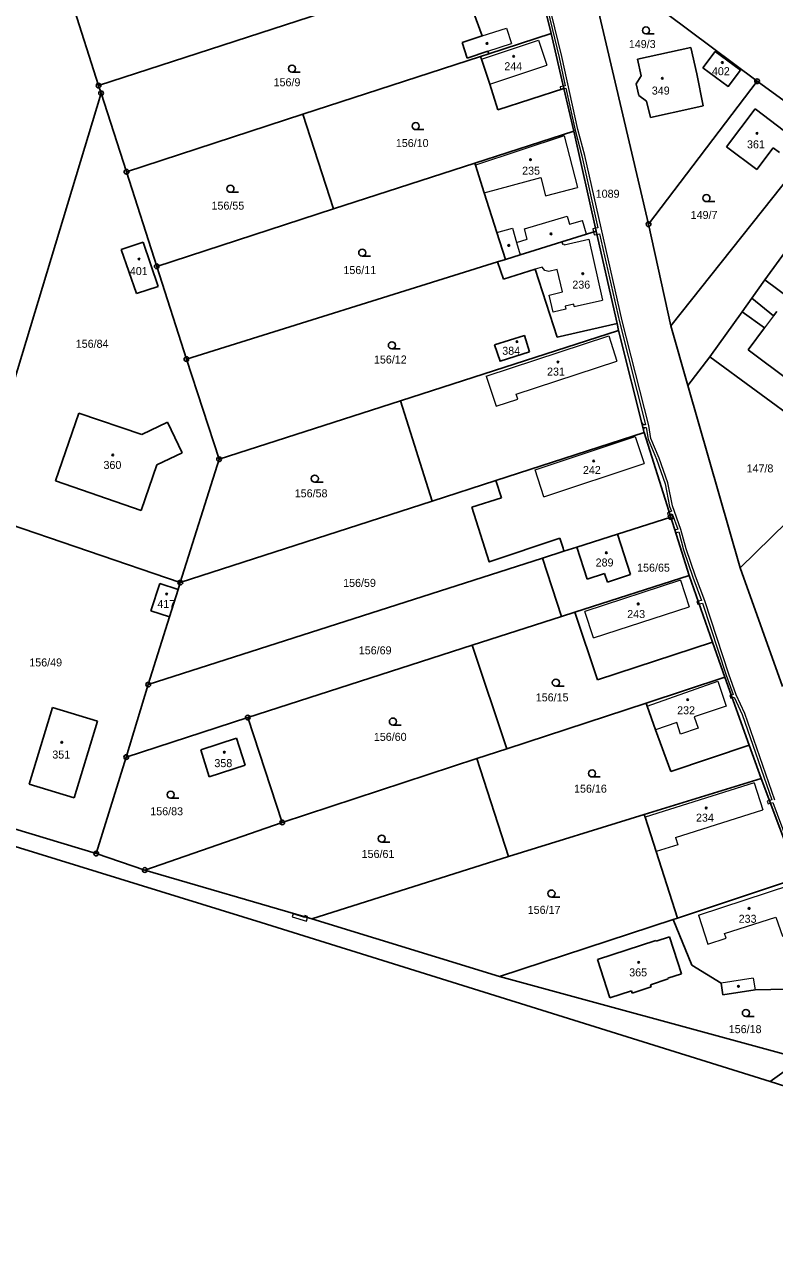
# Model space of a CAD drawing. Extents: x -694609 to -690140, y -1033292 to -1029794.
# Drawn here: x -693108.5 to -692949.2, y -1031786.2 to -1031527.4 of the extents above; entities that cross this region are included whole.
import ezdxf
from ezdxf.enums import TextEntityAlignment as Align

# ---------------------------------------------------------------- set-up
doc = ezdxf.new("R2010")
doc.units = 0
doc.header["$LTSCALE"] = 0.68
for name, color, linetype, lineweight in [('1', 7, 'Continuous', 25), ('13', 7, 'Continuous', 13), ('3', 7, 'Continuous', 25), ('4', 7, 'Continuous', 13), ('5', 7, 'Continuous', 25), ('8', 7, 'Continuous', 25)]:
    doc.layers.add(name, color=color, linetype=linetype, lineweight=lineweight)
doc.layers.add('2', color=7, linetype='Continuous')

msp = doc.modelspace()

# ---------------------------------------------------------------- linework, layer by layer
at = {"layer": '1'}
for p, q in [((-692996.59, -1031529.38), (-693001.15, -1031510.6)), ((-692982.32, -1031517.41), (-692952.88, -1031539.48)), ((-693032.75, -1031520.89), (-693092.7, -1031540.43)), ((-693014.39, -1031521.24), (-693011.22, -1031529.87)), ((-693092.7, -1031540.43), (-693098.34, -1031522.85)), ((-692975.92, -1031569.87), (-692987.13, -1031522.11)), ((-693009.82, -1031533.69), (-692996.59, -1031529.38)), ((-692996.59, -1031529.38), (-692993.89, -1031541.03)), ((-693015.51, -1031531.27), (-693011.22, -1031529.87)), ((-693014.44, -1031534.56), (-693015.51, -1031531.27)), ((-693049.32, -1031546.52), (-693011.57, -1031534.26)), ((-693014.44, -1031534.56), (-693010.03, -1031533.12)), ((-693011.57, -1031534.26), (-693009.82, -1031533.69)), ((-693011.39, -1031534.77), (-693011.57, -1031534.26)), ((-693010.03, -1031533.12), (-693009.82, -1031533.69)), ((-692966.91, -1031532.31), (-692978.28, -1031534.82)), ((-692965.67, -1031537.94), (-692966.91, -1031532.31)), ((-693011.39, -1031534.77), (-693009.62, -1031540.12)), ((-692978.28, -1031534.82), (-692977.51, -1031538.37)), ((-692977.51, -1031538.37), (-692978.57, -1031540.08)), ((-692975.92, -1031569.87), (-692952.88, -1031539.48)), ((-692964.32, -1031544.75), (-692965.67, -1031537.94)), ((-692938.37, -1031550.06), (-692952.88, -1031539.48)), ((-693092.18, -1031542.05), (-693137.04, -1031690.35)), ((-693092.18, -1031542.05), (-693092.7, -1031540.43)), ((-693086.77, -1031558.74), (-693092.18, -1031542.05)), ((-693009.62, -1031540.12), (-693007.9, -1031545.56)), ((-693007.9, -1031545.56), (-692993.89, -1031541.03)), ((-692993.89, -1031541.03), (-692991.79, -1031550.1)), ((-692978.57, -1031540.08), (-692978.01, -1031542.52)), ((-692978.01, -1031542.52), (-692976.32, -1031543.72)), ((-692976.32, -1031543.72), (-692975.53, -1031547.21)), ((-692966.55, -1031545.23), (-692964.32, -1031544.75)), ((-693086.77, -1031558.74), (-693049.32, -1031546.52)), ((-693049.32, -1031546.52), (-693042.84, -1031566.57)), ((-692975.53, -1031547.21), (-692966.55, -1031545.23)), ((-692959.34, -1031553.42), (-692953.28, -1031545.38)), ((-692953.28, -1031545.38), (-692945.56, -1031551.2)), ((-692991.79, -1031550.1), (-693012.81, -1031556.88)), ((-692987.06, -1031571.33), (-692991.79, -1031550.1)), ((-692938.37, -1031550.06), (-692971.22, -1031591.47)), ((-692952.95, -1031558.23), (-692959.34, -1031553.42)), ((-692949.47, -1031553.61), (-692952.95, -1031558.23)), ((-692948.12, -1031554.62), (-692949.47, -1031553.61)), ((-693012.81, -1031556.88), (-693042.84, -1031566.57)), ((-693012.81, -1031556.88), (-693012.69, -1031557.29)), ((-693012.69, -1031557.29), (-693010.84, -1031563.21)), ((-693080.36, -1031578.82), (-693086.77, -1031558.74)), ((-693010.84, -1031563.21), (-693008.14, -1031571.66)), ((-692939.33, -1031565.31), (-692951.21, -1031581.69)), ((-693042.84, -1031566.57), (-693080.36, -1031578.82)), ((-692971.22, -1031591.47), (-692975.92, -1031569.87)), ((-693008.14, -1031571.66), (-693006.32, -1031577.35)), ((-692989.09, -1031571.97), (-692994.33, -1031573.61)), ((-692987.06, -1031571.33), (-692989.09, -1031571.97)), ((-692982.61, -1031590.99), (-692987.06, -1031571.33)), ((-693087.89, -1031575.21), (-693083.26, -1031573.68)), ((-693084.63, -1031584.58), (-693087.89, -1031575.21)), ((-693083.26, -1031573.68), (-693080.08, -1031583.08)), ((-693001.14, -1031575.73), (-693003.19, -1031576.37)), ((-692994.33, -1031573.61), (-693001.14, -1031575.73)), ((-693007.96, -1031577.86), (-693074.04, -1031598.52)), ((-693006.32, -1031577.35), (-693007.96, -1031577.86)), ((-693006.73, -1031581.52), (-693007.96, -1031577.86)), ((-693003.19, -1031576.37), (-693006.32, -1031577.35)), ((-693074.04, -1031598.52), (-693080.36, -1031578.82)), ((-692999.96, -1031579.41), (-693006.73, -1031581.52)), ((-692999.96, -1031579.41), (-692995.35, -1031593.86)), ((-693080.08, -1031583.08), (-693084.63, -1031584.58)), ((-692953.98, -1031585.61), (-692951.21, -1031581.69)), ((-692951.21, -1031581.69), (-692920.32, -1031604.87)), ((-692956.05, -1031588.46), (-692953.98, -1031585.61)), ((-692949.38, -1031589.37), (-692953.98, -1031585.61)), ((-692962.9, -1031598.03), (-692956.05, -1031588.46)), ((-692951.27, -1031591.88), (-692956.05, -1031588.46)), ((-692948.67, -1031588.42), (-692949.38, -1031589.37)), ((-692995.35, -1031593.86), (-692982.61, -1031590.99)), ((-692982.28, -1031592.45), (-692982.61, -1031590.99)), ((-692967.59, -1031604.13), (-692971.22, -1031591.47)), ((-693028.58, -1031607.39), (-692982.28, -1031592.45)), ((-692976.87, -1031614.09), (-692982.28, -1031592.45)), ((-692951.27, -1031591.88), (-692954.78, -1031596.58)), ((-692954.78, -1031596.58), (-692945.81, -1031603.31)), ((-693067.1, -1031619.81), (-693074.04, -1031598.52)), ((-692962.9, -1031598.03), (-692967.59, -1031604.13)), ((-692933.59, -1031619.64), (-692962.9, -1031598.03)), ((-692956.5, -1031642.88), (-692967.59, -1031604.13)), ((-693058.18, -1031718.22), (-693416.83, -1031607.47)), ((-693067.1, -1031619.81), (-693028.58, -1031607.39)), ((-693028.58, -1031607.39), (-693021.89, -1031628.69)), ((-693096.87, -1031610.05), (-693101.84, -1031624.4)), ((-693083.5, -1031614.53), (-693096.87, -1031610.05)), ((-693078.05, -1031611.96), (-693083.5, -1031614.53)), ((-693074.92, -1031618.41), (-693078.05, -1031611.96)), ((-692976.87, -1031614.09), (-693008.34, -1031624.3)), ((-692971.22, -1031632.08), (-692976.87, -1031614.09)), ((-693080.3, -1031621.02), (-693074.92, -1031618.41)), ((-693075.34, -1031646.02), (-693067.1, -1031619.81)), ((-693083.63, -1031630.7), (-693080.3, -1031621.02)), ((-693101.84, -1031624.4), (-693083.63, -1031630.7)), ((-693008.34, -1031624.3), (-693021.89, -1031628.69)), ((-693007.16, -1031628.01), (-693008.34, -1031624.3)), ((-693021.89, -1031628.69), (-693075.34, -1031646.02)), ((-693013.44, -1031629.97), (-693007.16, -1031628.01)), ((-692956.5, -1031642.88), (-692942.66, -1031629.3)), ((-693114.36, -1031632.65), (-693075.34, -1031646.02)), ((-692971.22, -1031632.08), (-692982.48, -1031635.69)), ((-692967.28, -1031644.48), (-692971.22, -1031632.08)), ((-692982.48, -1031635.69), (-692991.13, -1031638.47)), ((-692979.72, -1031644.3), (-692982.48, -1031635.69)), ((-692994.79, -1031636.57), (-692994.08, -1031638.71)), ((-692998.42, -1031640.85), (-693082.14, -1031667.69)), ((-692993.88, -1031639.35), (-692998.42, -1031640.85)), ((-692998.42, -1031640.85), (-692994.42, -1031653.21)), ((-692994.08, -1031638.71), (-692993.88, -1031639.35)), ((-692991.13, -1031638.47), (-692993.88, -1031639.35)), ((-692991.13, -1031638.47), (-692988.94, -1031645.28)), ((-692947.47, -1031668.1), (-692956.5, -1031642.88)), ((-692967.28, -1031644.48), (-692991.55, -1031652.29)), ((-692988.94, -1031645.28), (-692985.25, -1031644.1)), ((-692985.25, -1031644.1), (-692984.67, -1031645.89)), ((-692984.67, -1031645.89), (-692979.72, -1031644.3)), ((-692962.32, -1031658.64), (-692967.28, -1031644.48)), ((-693081.58, -1031652.04), (-693079.72, -1031646.22)), ((-693079.72, -1031646.22), (-693075.8, -1031647.47)), ((-693077.62, -1031653.29), (-693082.14, -1031667.69)), ((-693077.62, -1031653.29), (-693081.58, -1031652.04)), ((-692994.42, -1031653.21), (-693013.35, -1031659.31)), ((-692991.55, -1031652.29), (-692994.42, -1031653.21)), ((-692991.55, -1031652.29), (-692986.76, -1031666.7)), ((-692986.76, -1031666.7), (-692962.32, -1031658.64)), ((-692959.71, -1031666.1), (-692962.32, -1031658.64)), ((-693013.35, -1031659.31), (-693061.03, -1031674.69)), ((-693013.35, -1031659.31), (-693006.04, -1031681.32)), ((-692976.45, -1031671.6), (-692959.71, -1031666.1)), ((-692954.52, -1031680.58), (-692959.71, -1031666.1)), ((-693086.84, -1031683.08), (-693082.14, -1031667.69)), ((-693006.04, -1031681.32), (-692976.45, -1031671.6)), ((-692976.22, -1031672.24), (-692976.45, -1031671.6)), ((-693107.47, -1031688.82), (-693102.49, -1031672.52)), ((-693102.49, -1031672.52), (-693092.93, -1031675.45)), ((-692976.22, -1031672.24), (-692974.44, -1031677.28)), ((-693092.93, -1031675.45), (-693097.9, -1031691.72)), ((-693086.84, -1031683.08), (-693061.03, -1031674.69)), ((-693061.03, -1031674.69), (-693053.69, -1031696.97)), ((-693071, -1031681.54), (-693063.4, -1031679.06)), ((-693063.4, -1031679.06), (-693061.54, -1031684.8)), ((-692974.44, -1031677.28), (-692971.19, -1031686.15)), ((-693071, -1031681.54), (-693069.19, -1031687.28)), ((-693012.37, -1031683.38), (-693006.04, -1031681.32)), ((-693093.2, -1031703.58), (-693086.84, -1031683.08)), ((-693069.19, -1031687.28), (-693061.54, -1031684.8)), ((-693053.69, -1031696.97), (-693012.37, -1031683.38)), ((-693012.37, -1031683.38), (-693005.65, -1031704.18)), ((-693097.9, -1031691.72), (-693107.47, -1031688.82)), ((-692976.82, -1031695.29), (-692951.99, -1031687.63)), ((-692944.11, -1031708.76), (-692951.99, -1031687.63)), ((-693132.25, -1031691.79), (-693093.2, -1031703.58)), ((-693082.89, -1031707.08), (-693053.69, -1031696.97)), ((-693005.65, -1031704.18), (-692976.82, -1031695.29)), ((-692976.62, -1031695.82), (-692976.82, -1031695.29)), ((-692974.33, -1031703.16), (-692976.62, -1031695.82)), ((-693093.2, -1031703.58), (-693082.89, -1031707.08)), ((-693047.4, -1031717.46), (-693005.65, -1031704.18)), ((-692974.33, -1031703.16), (-692969.74, -1031717.28)), ((-693047.4, -1031717.46), (-693082.89, -1031707.08)), ((-692944.11, -1031708.76), (-692969.74, -1031717.28)), ((-692950.08, -1031751.98), (-693058.18, -1031718.22)), ((-693007.59, -1031729.72), (-693047.4, -1031717.46)), ((-693007.59, -1031729.72), (-692970.7, -1031717.6)), ((-692969.74, -1031717.28), (-692970.7, -1031717.6)), ((-692970.7, -1031717.6), (-692966.75, -1031727.27)), ((-692986.78, -1031726.11), (-692974.37, -1031722.09)), ((-692974.37, -1031722.09), (-692974.33, -1031722.2)), ((-692974.33, -1031722.2), (-692971.5, -1031721.25)), ((-692971.5, -1031721.25), (-692968.94, -1031729.11)), ((-692984.14, -1031734.25), (-692986.78, -1031726.11)), ((-692966.75, -1031727.27), (-692960.53, -1031731.14)), ((-692946.57, -1031746.38), (-693007.59, -1031729.72)), ((-692971.75, -1031730.2), (-692975.52, -1031731.46)), ((-692975.52, -1031731.46), (-692975.37, -1031731.92)), ((-692968.94, -1031729.11), (-692971.8, -1031730.06)), ((-692971.8, -1031730.06), (-692971.75, -1031730.2)), ((-692960.53, -1031731.14), (-692960.18, -1031733.58)), ((-692979.56, -1031732.76), (-692984.14, -1031734.25)), ((-692979.41, -1031733.24), (-692979.56, -1031732.76)), ((-692975.37, -1031731.92), (-692979.41, -1031733.24)), ((-692953.28, -1031732.56), (-692960.18, -1031733.58)), ((-692953.28, -1031732.56), (-692939.76, -1031732.28)), ((-692950.08, -1031751.98), (-692943.65, -1031747.39)), ((-692846.26, -1031786.25), (-692950.08, -1031751.98))]:
    msp.add_line(p, q, dxfattribs=at)
for points in [[(-692964.38, -1031536.63), (-692961.77, -1031533.18), (-692956.43, -1031537.17)], [(-692956.43, -1031537.17), (-692959, -1031540.59), (-692964.38, -1031536.63)], [(-693001.23, -1031596.98), (-693002.26, -1031593.54), (-693008.63, -1031595.51)], [(-693008.63, -1031595.51), (-693007.46, -1031599), (-693001.23, -1031596.98)], [(-692994.79, -1031636.57), (-693009.74, -1031641.62), (-693013.44, -1031629.97)], [(-693075.34, -1031646.02), (-693075.8, -1031647.47), (-693077.62, -1031653.29)], [(-692951.99, -1031687.63), (-692954.52, -1031680.58), (-692971.19, -1031686.15)]]:
    msp.add_lwpolyline(points, dxfattribs=at)
at = {"layer": '13'}
for points in [[(-693000.38, -1031511.8), (-692994.88, -1031534.47), (-692993.59, -1031540.48), (-692994, -1031540.55), (-692993.89, -1031541.03), (-692993.49, -1031540.96), (-692991.49, -1031549.87), (-692990.06, -1031555.37), (-692986.66, -1031570.62), (-692987.19, -1031570.74), (-692986.9, -1031572.03), (-692986.35, -1031571.93), (-692982.06, -1031590.61), (-692976.55, -1031612.47), (-692977.04, -1031612.49), (-692977.12, -1031612.16), (-692977.34, -1031612.21), (-692977.05, -1031613.38)], [(-692949.07, -1031692.23), (-692955.48, -1031673.83), (-692957.32, -1031669.87), (-692958.87, -1031665.47), (-692963.98, -1031649.9), (-692965.95, -1031644.64), (-692967.91, -1031638.83), (-692969.04, -1031634.72), (-692970.86, -1031629.68), (-692971.8, -1031624.84), (-692973.67, -1031619.61), (-692975.4, -1031615.4), (-692975.88, -1031612.67), (-692981.49, -1031590.43), (-692989.47, -1031555.28), (-692990.9, -1031549.77), (-692994.31, -1031534.27), (-692999.62, -1031512.42)], [(-692977.05, -1031613.38), (-692976.84, -1031613.33), (-692976.9, -1031613.09), (-692976.42, -1031613.07), (-692975.98, -1031615.57), (-692974.23, -1031619.82), (-692972.38, -1031625), (-692971.44, -1031629.83), (-692971.08, -1031630.84), (-692971.54, -1031631.06), (-692971.36, -1031631.63), (-692970.89, -1031631.39), (-692969.71, -1031634.64), (-692970.34, -1031634.86), (-692970.16, -1031635.43), (-692969.52, -1031635.21), (-692968.48, -1031639.02), (-692966.51, -1031644.87), (-692964.65, -1031649.81), (-692965.35, -1031649.98), (-692965.16, -1031650.54), (-692964.45, -1031650.38), (-692959.43, -1031665.7), (-692957.98, -1031669.79), (-692958.34, -1031669.92), (-692958.14, -1031670.48), (-692957.76, -1031670.34), (-692956.04, -1031674.05), (-692949.73, -1031692.17), (-692950.24, -1031692.33), (-692950.03, -1031692.89), (-692949.53, -1031692.73), (-692946.53, -1031700.76)]]:
    msp.add_lwpolyline(points, dxfattribs=at)
for points in [[(-692994.7, -1031540.68), (-692994.59, -1031541.26), (-692993.89, -1031541.03), (-692994, -1031540.55)], [(-692987.58, -1031571.49), (-692987.06, -1031571.33), (-692987.19, -1031570.74), (-692987.72, -1031570.85)], [(-692987.58, -1031571.49), (-692987.44, -1031572.12), (-692986.9, -1031572.03), (-692987.06, -1031571.33)], [(-692971.92, -1031631.24), (-692971.76, -1031631.83), (-692971.36, -1031631.63), (-692971.54, -1031631.06)], [(-692965.67, -1031650.05), (-692965.49, -1031650.62), (-692965.16, -1031650.54), (-692965.35, -1031649.98)], [(-692958.65, -1031670.03), (-692958.43, -1031670.59), (-692958.14, -1031670.48), (-692958.34, -1031669.92)], [(-692950.71, -1031692.47), (-692950.52, -1031693.04), (-692950.03, -1031692.89), (-692950.24, -1031692.33)], [(-693051.38, -1031716.42), (-693051.56, -1031717), (-693048.57, -1031717.95), (-693048.37, -1031717.18), (-693048.95, -1031717.01), (-693048.99, -1031717.19)], [(-693048.95, -1031717.01), (-693048.37, -1031717.18), (-693048.32, -1031716.95), (-693048.89, -1031716.78)]]:
    msp.add_lwpolyline(points, close=True, dxfattribs=at)
at = {"layer": '3'}
for p, q in [((-692976.463, -1031529.44), (-692974.713, -1031529.44)), ((-693051.633, -1031537.57), (-693049.883, -1031537.57)), ((-693025.353, -1031549.78), (-693023.603, -1031549.78)), ((-693064.703, -1031563.09), (-693062.953, -1031563.09)), ((-692963.623, -1031565.08), (-692961.873, -1031565.08)), ((-693036.713, -1031576.68), (-693034.963, -1031576.68)), ((-693030.413, -1031596.36), (-693028.663, -1031596.36)), ((-693046.783, -1031624.68), (-693045.033, -1031624.68)), ((-692995.603, -1031668.03), (-692993.853, -1031668.03)), ((-693030.203, -1031676.29), (-693028.453, -1031676.29)), ((-692987.913, -1031687.31), (-692986.163, -1031687.31)), ((-693077.393, -1031691.83), (-693075.643, -1031691.83)), ((-693032.573, -1031701.17), (-693030.823, -1031701.17)), ((-692996.533, -1031712.83), (-692994.783, -1031712.83)), ((-692955.253, -1031738.21), (-692953.503, -1031738.21))]:
    msp.add_line(p, q, dxfattribs=at)
for centre in [(-692976.4629, -1031528.6898), (-693051.6329, -1031536.8198), (-693025.3529, -1031549.0298), (-693064.7029, -1031562.3398), (-692963.6229, -1031564.3298), (-693036.7129, -1031575.9298), (-693030.4129, -1031595.6098), (-693046.7829, -1031623.9298), (-692995.6029, -1031667.2798), (-693030.2029, -1031675.5398), (-692987.9129, -1031686.5598), (-693077.3929, -1031691.0798), (-693032.5729, -1031700.4198), (-692996.5329, -1031712.0798), (-692955.2529, -1031737.4598)]:
    msp.add_circle(centre, 0.75, dxfattribs=at)
at = {"layer": '4'}
for p, q in [((-693011.22, -1031529.87), (-693006.06, -1031528.19)), ((-693006.06, -1031528.19), (-693004.99, -1031531.48)), ((-693010.03, -1031533.12), (-693004.99, -1031531.48)), ((-693009.62, -1031540.12), (-692997.51, -1031536.11)), ((-692993.84, -1031551.1), (-693012.69, -1031557.29)), ((-692993.84, -1031551.1), (-692990.99, -1031562.04)), ((-692997.78, -1031563.81), (-692990.99, -1031562.04)), ((-693008.14, -1031571.66), (-693004.8, -1031570.71)), ((-692989.09, -1031571.97), (-692989.92, -1031569.07)), ((-692993.84, -1031574.22), (-692988.62, -1031573.05)), ((-692988.62, -1031573.05), (-692985.72, -1031586.01)), ((-693003.94, -1031573.73), (-693003.19, -1031576.37)), ((-692994.33, -1031573.61), (-692994.22, -1031574.08)), ((-692994.22, -1031574.08), (-692993.9, -1031574.01)), ((-692993.9, -1031574.01), (-692993.84, -1031574.22)), ((-692998.54, -1031578.97), (-692999.96, -1031579.41)), ((-692997.93, -1031579.73), (-692998.54, -1031578.97)), ((-692997.1, -1031579.89), (-692997.93, -1031579.73)), ((-692995.29, -1031579.48), (-692997.1, -1031579.89)), ((-692994.16, -1031584.22), (-692995.29, -1031579.48)), ((-692997.04, -1031584.98), (-692994.16, -1031584.22)), ((-692996.16, -1031588.58), (-692997.04, -1031584.98)), ((-692991.7, -1031587.35), (-692985.72, -1031586.01)), ((-692993.49, -1031587.94), (-692996.16, -1031588.58)), ((-692991.81, -1031586.84), (-692993.65, -1031587.27)), ((-692993.65, -1031587.27), (-692993.49, -1031587.94)), ((-692991.7, -1031587.35), (-692991.81, -1031586.84)), ((-692949.38, -1031589.37), (-692951.27, -1031591.88)), ((-693010.4, -1031602.14), (-692984.38, -1031593.61)), ((-692984.38, -1031593.61), (-692982.63, -1031598.95)), ((-693004.01, -1031605.96), (-692982.63, -1031598.95)), ((-693010.4, -1031602.14), (-693008.3, -1031608.56)), ((-693008.3, -1031608.56), (-693003.66, -1031607.04)), ((-693003.66, -1031607.04), (-693004.01, -1031605.96)), ((-692978.77, -1031615), (-692976.87, -1031620.72)), ((-692998.13, -1031627.78), (-692976.87, -1031620.72)), ((-692969.1, -1031645.53), (-692989.43, -1031652.14)), ((-692969.1, -1031645.53), (-692967.28, -1031651.16)), ((-692987.61, -1031657.73), (-692967.28, -1031651.16)), ((-692987.61, -1031657.73), (-692989.43, -1031652.14)), ((-692976.22, -1031672.24), (-692961.2, -1031666.98)), ((-692961.2, -1031666.98), (-692959.41, -1031672.29)), ((-692959.41, -1031672.29), (-692966.2, -1031674.53)), ((-692969.94, -1031675.76), (-692974.44, -1031677.28)), ((-692969.12, -1031678.19), (-692969.94, -1031675.76)), ((-692965.37, -1031676.92), (-692969.12, -1031678.19)), ((-692966.2, -1031674.53), (-692965.37, -1031676.92)), ((-692953.47, -1031688.58), (-692976.62, -1031695.82)), ((-692953.47, -1031688.58), (-692951.66, -1031694.26)), ((-692970.17, -1031700.16), (-692951.66, -1031694.26)), ((-692970.17, -1031700.16), (-692969.69, -1031701.71)), ((-692969.69, -1031701.71), (-692974.33, -1031703.16)), ((-692965.33, -1031716.68), (-692963.34, -1031722.82)), ((-692959.46, -1031721.54), (-692959.77, -1031720.59)), ((-692963.34, -1031722.82), (-692959.46, -1031721.54)), ((-692953.68, -1031730.06), (-692960.53, -1031731.14)), ((-692953.68, -1031730.06), (-692953.28, -1031732.56))]:
    msp.add_line(p, q, dxfattribs=at)
for points in [[(-693011.39, -1031534.77), (-692999.28, -1031530.76), (-692997.51, -1031536.11)], [(-693010.84, -1031563.21), (-692998.8, -1031559.95), (-692997.78, -1031563.81)], [(-693002.28, -1031570.85), (-692993.17, -1031568.19), (-692992.69, -1031569.86), (-692989.92, -1031569.07)], [(-693004.8, -1031570.71), (-693003.94, -1031573.73), (-693001.67, -1031573.07), (-693002.28, -1031570.85)], [(-692998.13, -1031627.78), (-693000.02, -1031622.06), (-692978.77, -1031615)], [(-692965.33, -1031716.68), (-692945.72, -1031710.21), (-692942.67, -1031719.46)], [(-692959.77, -1031720.59), (-692948.86, -1031717.09), (-692947.46, -1031721.11), (-692942.67, -1031719.46)]]:
    msp.add_lwpolyline(points, dxfattribs=at)
at = {"layer": '5'}
for centre in [(-693010.2268, -1031531.4592), (-693004.5468, -1031534.1992), (-692960.2668, -1031535.5192), (-692973.0068, -1031538.8692), (-692952.8968, -1031550.5792), (-693000.9868, -1031556.1492), (-692996.6368, -1031571.9292), (-693005.5968, -1031574.3892), (-693084.1168, -1031577.2792), (-692989.8768, -1031580.3892), (-693003.8468, -1031594.8192), (-692995.1368, -1031599.1492), (-693089.6768, -1031618.8992), (-692987.5768, -1031620.1692), (-692984.8768, -1031639.6792), (-693078.2268, -1031648.4392), (-692978.1068, -1031650.5392), (-692967.6168, -1031670.8792), (-693100.5168, -1031679.9492), (-693065.9868, -1031682.0492), (-692963.6768, -1031693.9192), (-692954.5568, -1031715.2492), (-692978.0268, -1031726.7092), (-692956.8368, -1031731.8092)]:
    msp.add_circle(centre, 0.175, dxfattribs=at)
at = {"layer": '8'}
for centre, radius in [((-692952.88, -1031539.4799), 0.5), ((-692952.88, -1031539.4799), 0.0303), ((-693092.7, -1031540.4299), 0.5), ((-693092.7, -1031540.4299), 0.0303), ((-693092.18, -1031542.0499), 0.5), ((-693092.18, -1031542.0499), 0.0303), ((-693086.77, -1031558.7399), 0.5), ((-693086.77, -1031558.7399), 0.0303), ((-692975.92, -1031569.8699), 0.5), ((-692975.92, -1031569.8699), 0.0303), ((-693080.36, -1031578.8199), 0.5), ((-693080.36, -1031578.8199), 0.0303), ((-693074.04, -1031598.5199), 0.5), ((-693074.04, -1031598.5199), 0.0303), ((-693067.1, -1031619.8099), 0.5), ((-693067.1, -1031619.8099), 0.0303), ((-692971.22, -1031632.0799), 0.5), ((-692971.22, -1031632.0799), 0.0303), ((-693075.34, -1031646.0199), 0.5), ((-693075.34, -1031646.0199), 0.0303), ((-693082.14, -1031667.6899), 0.5), ((-693082.14, -1031667.6899), 0.0303), ((-693061.03, -1031674.6899), 0.5), ((-693061.03, -1031674.6899), 0.0303), ((-693086.84, -1031683.0799), 0.5), ((-693086.84, -1031683.0799), 0.0303), ((-693053.69, -1031696.9699), 0.5), ((-693053.69, -1031696.9699), 0.0303), ((-693093.2, -1031703.5799), 0.5), ((-693093.2, -1031703.5799), 0.0303), ((-693082.89, -1031707.0799), 0.5), ((-693082.89, -1031707.0799), 0.0303)]:
    msp.add_circle(centre, radius, dxfattribs=at)

# ---------------------------------------------------------------- texts
at = {"layer": '2'}
for s, p in [('149/3', (-692977.26, -1031532.445)), ('244', (-693004.649, -1031537.155)), ('402', (-692960.569, -1031538.212)), ('156/9', (-693052.69, -1031540.565)), ('349', (-692973.329, -1031542.325)), ('156/10', (-693026.1, -1031553.475)), ('361', (-692953.119, -1031553.755)), ('235', (-693000.869, -1031559.345)), ('1089', (-692984.61, -1031564.245)), ('156/55', (-693065.24, -1031566.775)), ('149/7', (-692964.13, -1031568.755)), ('156/11', (-693037.23, -1031580.465)), ('401', (-693084.169, -1031580.672)), ('236', (-692990.209, -1031583.555)), ('156/84', (-693094.07, -1031596.125)), ('384', (-693005.089, -1031597.612)), ('156/12', (-693030.75, -1031599.465)), ('231', (-692995.579, -1031602.035)), ('360', (-693089.759, -1031621.865)), ('242', (-692987.959, -1031622.945)), ('147/8', (-692952.26, -1031622.605)), ('156/58', (-693047.57, -1031627.895)), ('289', (-692985.259, -1031642.595)), ('156/65', (-692974.87, -1031643.695)), ('156/59', (-693037.29, -1031646.925)), ('243', (-692978.549, -1031653.545)), ('156/69', (-693033.97, -1031661.255)), ('156/49', (-693103.93, -1031663.825)), ('156/15', (-692996.39, -1031671.255)), ('232', (-692967.949, -1031673.995)), ('156/60', (-693030.77, -1031679.635)), ('351', (-693100.629, -1031683.405)), ('358', (-693066.209, -1031685.225)), ('156/16', (-692988.26, -1031690.645)), ('156/83', (-693078.24, -1031695.455)), ('234', (-692963.949, -1031696.815)), ('156/61', (-693033.36, -1031704.515)), ('156/17', (-692998.1, -1031716.395)), ('233', (-692954.889, -1031718.295)), ('365', (-692978.129, -1031729.685)), ('156/18', (-692955.41, -1031741.745))]:
    msp.add_text(s, height=1.7, dxfattribs=at).set_placement(p, align=Align.CENTER)
msp.add_text('417', height=1.7, dxfattribs=at).set_placement((-693080.22, -1031651.405))

doc.saveas('drawing.dxf')
